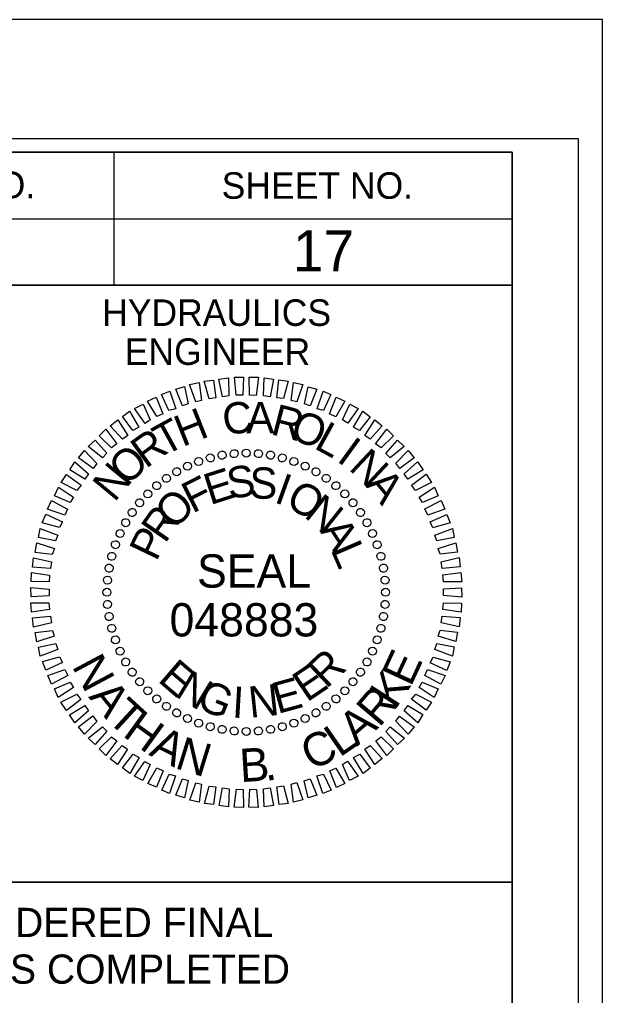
# Model space of a CAD drawing. Extents: x 1647943 to 1651624, y 802691 to 845761.
# Drawn here: x 1650436.5 to 1650546.3, y 803607.1 to 803791 of the extents above; entities that cross this region are included whole.
import ezdxf

# ---------------------------------------------------------------- set-up
doc = ezdxf.new("R2010")
doc.units = 0
for name, color, linetype in [('Default', 7, 'Continuous'), ('Old_Level_2', 7, 'Continuous'), ('Sheet Cutting Line CELL', 7, 'Continuous'), ('Sheet Data Field CELL', 7, 'Continuous'), ('Sheet Plot Border Inside CELL', 7, 'Continuous'), ('Sheet Plot Border Outside CELL', 7, 'Continuous'), ('Sheet Profile CELL', 7, 'Continuous'), ('Sheet Profile Grid Major CELL', 7, 'Continuous'), ('Sheet Sticker Exception Certification CELL', 7, 'Continuous')]:
    doc.layers.add(name, color=color, linetype=linetype)

msp = doc.modelspace()

# ---------------------------------------------------------------- linework, layer by layer
at = {"layer": 'Old_Level_2'}
for p, q in [((1650476.94, 803709.25), (1650476.94, 803709.25)), ((1650479.24, 803709.34), (1650479.24, 803709.34)), ((1650481.55, 803709.22), (1650481.55, 803709.22)), ((1650470.22, 803707.77), (1650470.22, 803707.77)), ((1650472.41, 803708.44), (1650472.41, 803708.44)), ((1650474.7, 803708.89), (1650474.7, 803708.89)), ((1650483.8, 803708.9), (1650483.8, 803708.9)), ((1650486.01, 803708.46), (1650486.01, 803708.46)), ((1650488.21, 803707.77), (1650488.21, 803707.77)), ((1650466.13, 803705.82), (1650466.13, 803705.82)), ((1650468.15, 803706.9), (1650468.15, 803706.9)), ((1650490.32, 803706.87), (1650490.32, 803706.87)), ((1650492.38, 803705.86), (1650492.38, 803705.86)), ((1650464.16, 803704.58), (1650464.16, 803704.58)), ((1650494.28, 803704.58), (1650494.28, 803704.58)), ((1650460.66, 803701.64), (1650460.66, 803701.64)), ((1650462.35, 803703.24), (1650462.35, 803703.24)), ((1650496.14, 803703.2), (1650496.14, 803703.2)), ((1650497.79, 803701.66), (1650497.79, 803701.66)), ((1650459.12, 803699.99), (1650459.12, 803699.99)), ((1650499.38, 803699.96), (1650499.38, 803699.96)), ((1650457.74, 803698.14), (1650457.74, 803698.14)), ((1650500.72, 803698.16), (1650500.72, 803698.16)), ((1650456.46, 803696.23), (1650456.46, 803696.23)), ((1650501.96, 803696.19), (1650501.96, 803696.19)), ((1650455.45, 803694.18), (1650455.45, 803694.18)), ((1650503.04, 803694.17), (1650503.04, 803694.17)), ((1650454.55, 803692.07), (1650454.55, 803692.07)), ((1650503.91, 803692.09), (1650503.91, 803692.09)), ((1650453.85, 803689.86), (1650453.85, 803689.86)), ((1650504.58, 803689.91), (1650504.58, 803689.91)), ((1650453.42, 803687.66), (1650453.42, 803687.66)), ((1650505.04, 803687.62), (1650505.04, 803687.62)), ((1650453.1, 803685.4), (1650453.1, 803685.4)), ((1650505.39, 803685.37), (1650505.39, 803685.37)), ((1650452.98, 803683.1), (1650452.98, 803683.1)), ((1650479.23, 803683.09), (1650479.23, 803683.09)), ((1650505.48, 803683.07), (1650505.48, 803683.07)), ((1650453.07, 803680.8), (1650453.07, 803680.8)), ((1650505.37, 803680.77), (1650505.37, 803680.77)), ((1650453.42, 803678.56), (1650453.42, 803678.56)), ((1650505.04, 803678.52), (1650505.04, 803678.52)), ((1650453.88, 803676.26), (1650453.88, 803676.26)), ((1650504.61, 803676.31), (1650504.61, 803676.31)), ((1650454.55, 803674.08), (1650454.55, 803674.08)), ((1650503.92, 803674.1), (1650503.92, 803674.1)), ((1650455.42, 803672), (1650455.42, 803672)), ((1650503.01, 803672), (1650503.01, 803672)), ((1650456.5, 803669.98), (1650456.5, 803669.98)), ((1650502, 803669.94), (1650502, 803669.94)), ((1650457.74, 803668.02), (1650457.74, 803668.02)), ((1650500.73, 803668.03), (1650500.73, 803668.03)), ((1650459.08, 803666.21), (1650459.08, 803666.21)), ((1650499.35, 803666.18), (1650499.35, 803666.18)), ((1650460.68, 803664.51), (1650460.68, 803664.51)), ((1650497.81, 803664.53), (1650497.81, 803664.53)), ((1650462.32, 803662.97), (1650462.32, 803662.97)), ((1650464.18, 803661.59), (1650464.18, 803661.59)), ((1650494.3, 803661.59), (1650494.3, 803661.59)), ((1650496.11, 803662.93), (1650496.11, 803662.93)), ((1650466.08, 803660.32), (1650466.08, 803660.32)), ((1650468.14, 803659.31), (1650468.14, 803659.31)), ((1650492.34, 803660.36), (1650492.34, 803660.36)), ((1650470.25, 803658.4), (1650470.25, 803658.4)), ((1650472.46, 803657.71), (1650472.46, 803657.71)), ((1650486.05, 803657.74), (1650486.05, 803657.74)), ((1650488.24, 803658.4), (1650488.24, 803658.4)), ((1650490.32, 803659.28), (1650490.32, 803659.28)), ((1650474.66, 803657.28), (1650474.66, 803657.28)), ((1650476.92, 803656.95), (1650476.92, 803656.95)), ((1650479.22, 803656.83), (1650479.22, 803656.83)), ((1650481.52, 803656.93), (1650481.52, 803656.93)), ((1650483.76, 803657.28), (1650483.76, 803657.28))]:
    msp.add_line(p, q, dxfattribs=at)
for points in [[(1650467.22, 803718.23), (1650465.96, 803721.34), (1650467.57, 803721.84), (1650468.31, 803718.61)], [(1650469.71, 803718.95), (1650468.56, 803722.23), (1650470.33, 803722.62), (1650470.81, 803719.23)], [(1650472.21, 803719.57), (1650471.32, 803722.9), (1650473.04, 803723.09), (1650473.47, 803719.75)], [(1650474.72, 803719.93), (1650474.08, 803723.26), (1650475.86, 803723.5), (1650475.97, 803720.11)], [(1650477.33, 803720.24), (1650477.01, 803723.63), (1650478.73, 803723.61), (1650478.58, 803720.21)], [(1650479.84, 803720.23), (1650479.78, 803723.63), (1650481.5, 803723.6), (1650481.09, 803720.2)], [(1650482.45, 803720.12), (1650482.6, 803723.52), (1650484.34, 803723.23), (1650483.71, 803719.93)], [(1650484.97, 803719.74), (1650485.38, 803723.1), (1650487.11, 803722.86), (1650486.23, 803719.61)], [(1650487.65, 803719.21), (1650488.11, 803722.62), (1650489.9, 803722.23), (1650488.75, 803718.97)], [(1650464.67, 803717.35), (1650463.26, 803720.36), (1650464.82, 803721.01), (1650465.97, 803717.68)], [(1650490.17, 803718.58), (1650490.9, 803721.83), (1650492.53, 803721.34), (1650491.27, 803718.23)], [(1650492.54, 803717.68), (1650493.68, 803720.99), (1650495.16, 803720.39), (1650493.75, 803717.33)], [(1650460.16, 803714.92), (1650458.18, 803717.71), (1650459.79, 803718.57), (1650461.15, 803715.56)], [(1650462.39, 803716.21), (1650460.66, 803719.11), (1650462.27, 803719.87), (1650463.53, 803716.7)], [(1650494.91, 803716.72), (1650496.16, 803719.83), (1650497.79, 803719.13), (1650496.07, 803716.17)], [(1650497.33, 803715.56), (1650498.69, 803718.57), (1650500.28, 803717.71), (1650498.34, 803714.95)], [(1650457.89, 803713.57), (1650455.9, 803716.2), (1650457.25, 803717.22), (1650459.02, 803714.22)], [(1650499.4, 803714.19), (1650501.17, 803717.25), (1650502.55, 803716.18), (1650500.56, 803713.58)], [(1650455.93, 803711.97), (1650453.63, 803714.44), (1650455.03, 803715.56), (1650456.91, 803712.66)], [(1650501.57, 803712.66), (1650503.45, 803715.57), (1650504.83, 803714.44), (1650502.57, 803711.94)], [(1650453.86, 803710.31), (1650451.52, 803712.57), (1650452.76, 803713.85), (1650454.84, 803711.06)], [(1650503.58, 803711.07), (1650505.68, 803713.83), (1650506.96, 803712.59), (1650504.59, 803710.3)], [(1650452.17, 803708.45), (1650449.47, 803710.55), (1650450.75, 803711.77), (1650452.99, 803709.3)], [(1650505.5, 803709.27), (1650507.7, 803711.77), (1650508.98, 803710.54), (1650506.3, 803708.45)], [(1650450.37, 803706.43), (1650447.62, 803708.42), (1650448.75, 803709.8), (1650451.09, 803707.38)], [(1650507.36, 803707.42), (1650509.72, 803709.82), (1650510.85, 803708.43), (1650508.11, 803706.39)], [(1650448.84, 803704.42), (1650445.99, 803706.14), (1650446.95, 803707.68), (1650449.5, 803705.42)], [(1650508.96, 803705.41), (1650511.49, 803707.65), (1650512.51, 803706.15), (1650509.61, 803704.43)], [(1650447.31, 803702.3), (1650444.35, 803703.81), (1650445.37, 803705.3), (1650448.13, 803703.25)], [(1650510.36, 803703.29), (1650513.1, 803705.33), (1650514.12, 803703.78), (1650511.11, 803702.26)], [(1650446.09, 803700.03), (1650443.09, 803701.28), (1650443.85, 803702.92), (1650446.7, 803701.03)], [(1650511.76, 803701.02), (1650514.66, 803702.9), (1650515.36, 803701.29), (1650512.41, 803700.03)], [(1650445.09, 803697.6), (1650441.83, 803698.75), (1650442.58, 803700.38), (1650445.59, 803698.76)], [(1650512.85, 803698.79), (1650515.9, 803700.41), (1650516.61, 803698.75), (1650513.39, 803697.65)], [(1650444.08, 803695.29), (1650440.83, 803696.17), (1650441.48, 803697.8), (1650444.64, 803696.39)], [(1650513.83, 803696.35), (1650516.99, 803697.76), (1650517.6, 803696.15), (1650514.37, 803695.26)], [(1650443.34, 803692.76), (1650440.09, 803693.39), (1650440.43, 803695.12), (1650443.74, 803693.87)], [(1650514.71, 803693.85), (1650518.03, 803695.11), (1650518.38, 803693.39), (1650515.09, 803692.76)], [(1650442.71, 803690.24), (1650439.46, 803690.6), (1650439.79, 803692.39), (1650443.11, 803691.35)], [(1650515.38, 803691.35), (1650518.66, 803692.4), (1650519, 803690.63), (1650515.71, 803690.26)], [(1650442.34, 803687.57), (1650438.99, 803687.82), (1650439.16, 803689.6), (1650442.58, 803688.83)], [(1650515.89, 803688.85), (1650519.28, 803689.64), (1650519.47, 803687.87), (1650516.13, 803687.6)], [(1650442.12, 803685.05), (1650438.72, 803685.1), (1650438.79, 803686.83), (1650442.2, 803686.31)], [(1650516.25, 803686.35), (1650519.64, 803686.82), (1650519.78, 803685.05), (1650516.38, 803685.09)], [(1650442.11, 803682.44), (1650438.72, 803682.22), (1650438.69, 803684), (1650442.09, 803683.69)], [(1650516.35, 803683.73), (1650519.75, 803683.95), (1650519.78, 803682.17), (1650516.37, 803682.48)], [(1650442.21, 803679.83), (1650438.82, 803679.35), (1650438.68, 803681.12), (1650442.08, 803681.08)], [(1650516.34, 803681.12), (1650519.74, 803681.07), (1650519.67, 803679.35), (1650516.26, 803679.86)], [(1650442.57, 803677.32), (1650439.18, 803676.53), (1650438.99, 803678.3), (1650442.34, 803678.57)], [(1650516.13, 803678.61), (1650519.48, 803678.35), (1650519.3, 803676.57), (1650515.89, 803677.35)], [(1650443.08, 803674.82), (1650439.81, 803673.77), (1650439.46, 803675.54), (1650442.75, 803675.91)], [(1650515.75, 803675.93), (1650519, 803675.57), (1650518.67, 803673.79), (1650515.36, 803674.83)], [(1650443.75, 803672.32), (1650440.43, 803671.06), (1650440.08, 803672.78), (1650443.37, 803673.41)], [(1650515.12, 803673.41), (1650518.37, 803672.79), (1650518.04, 803671.06), (1650514.72, 803672.31)], [(1650444.63, 803669.83), (1650441.47, 803668.41), (1650440.86, 803670.02), (1650444.09, 803670.92)], [(1650514.38, 803670.89), (1650517.64, 803670), (1650516.98, 803668.37), (1650513.82, 803669.78)], [(1650445.62, 803667.39), (1650442.56, 803665.76), (1650441.85, 803667.42), (1650445.07, 803668.53)], [(1650513.37, 803668.57), (1650516.64, 803667.42), (1650515.88, 803665.79), (1650512.87, 803667.41)], [(1650446.7, 803665.16), (1650443.81, 803663.28), (1650443.1, 803664.88), (1650446.06, 803666.14)], [(1650512.37, 803666.15), (1650515.37, 803664.89), (1650514.62, 803663.26), (1650511.76, 803665.14)], [(1650448.1, 803662.88), (1650445.37, 803660.84), (1650444.34, 803662.4), (1650447.35, 803663.91)], [(1650511.15, 803663.88), (1650514.11, 803662.36), (1650513.09, 803660.88), (1650510.33, 803662.92)], [(1650449.5, 803660.76), (1650446.97, 803658.52), (1650445.96, 803660.02), (1650448.85, 803661.74)], [(1650509.62, 803661.76), (1650512.48, 803660.03), (1650511.51, 803658.5), (1650508.96, 803660.75)], [(1650451.1, 803658.75), (1650448.74, 803656.35), (1650447.62, 803657.75), (1650450.35, 803659.78)], [(1650508.09, 803659.74), (1650510.84, 803657.75), (1650509.72, 803656.37), (1650507.37, 803658.79)], [(1650452.97, 803656.9), (1650450.76, 803654.4), (1650449.48, 803655.63), (1650452.17, 803657.72)], [(1650506.29, 803657.72), (1650509, 803655.63), (1650507.71, 803654.4), (1650505.47, 803656.87)], [(1650454.88, 803655.1), (1650452.78, 803652.35), (1650451.51, 803653.58), (1650453.87, 803655.87)], [(1650504.6, 803655.86), (1650506.94, 803653.6), (1650505.71, 803652.33), (1650503.62, 803655.12)], [(1650456.89, 803653.52), (1650455.01, 803650.61), (1650453.63, 803651.73), (1650455.89, 803654.23)], [(1650502.54, 803654.21), (1650504.83, 803651.74), (1650503.44, 803650.61), (1650501.56, 803653.51)], [(1650459.06, 803651.98), (1650457.29, 803648.92), (1650455.91, 803649.99), (1650457.9, 803652.59)], [(1650500.58, 803652.6), (1650502.56, 803649.97), (1650501.22, 803648.95), (1650499.44, 803651.96)], [(1650461.13, 803650.61), (1650459.77, 803647.6), (1650458.18, 803648.46), (1650460.12, 803651.22)], [(1650498.3, 803651.26), (1650500.28, 803648.47), (1650498.68, 803647.6), (1650497.32, 803650.61)], [(1650463.55, 803649.45), (1650462.3, 803646.34), (1650460.67, 803647.04), (1650462.39, 803650)], [(1650465.92, 803648.5), (1650464.78, 803645.18), (1650463.3, 803645.78), (1650464.72, 803648.84)], [(1650493.79, 803648.82), (1650495.2, 803645.82), (1650493.65, 803645.16), (1650492.49, 803648.49)], [(1650496.07, 803649.96), (1650497.8, 803647.06), (1650496.19, 803646.3), (1650494.93, 803649.47)], [(1650468.29, 803647.6), (1650467.57, 803644.34), (1650465.94, 803644.83), (1650467.19, 803647.94)], [(1650470.81, 803646.96), (1650470.35, 803643.55), (1650468.57, 803643.94), (1650469.71, 803647.2)], [(1650473.49, 803646.43), (1650473.08, 803643.08), (1650471.35, 803643.31), (1650472.23, 803646.57)], [(1650486.25, 803646.6), (1650487.14, 803643.27), (1650485.42, 803643.08), (1650485, 803646.42)], [(1650488.75, 803647.22), (1650489.9, 803643.95), (1650488.13, 803643.55), (1650487.65, 803646.94)], [(1650491.25, 803647.94), (1650492.5, 803644.83), (1650490.89, 803644.33), (1650490.15, 803647.56)], [(1650476.01, 803646.06), (1650475.86, 803642.65), (1650474.13, 803642.94), (1650474.75, 803646.24)], [(1650478.62, 803645.95), (1650478.68, 803642.55), (1650476.96, 803642.57), (1650477.37, 803645.98)], [(1650481.13, 803645.94), (1650481.46, 803642.54), (1650479.73, 803642.57), (1650479.88, 803645.97)], [(1650483.74, 803646.24), (1650484.38, 803642.91), (1650482.6, 803642.67), (1650482.49, 803646.07)]]:
    msp.add_lwpolyline(points, close=True, dxfattribs=at)
for centre, major_axis in [((1650472.44, 803708.42), (-0.195, 0.727)), ((1650474.68, 803708.92), (-0.131, 0.742)), ((1650476.95, 803709.21), (-0.066, 0.75)), ((1650479.23, 803709.31), (0, 0.753)), ((1650481.52, 803709.21), (0.066, 0.75)), ((1650483.79, 803708.92), (0.131, 0.742)), ((1650486.02, 803708.42), (0.195, 0.727)), ((1650468.15, 803706.86), (-0.318, 0.682)), ((1650470.26, 803707.73), (-0.258, 0.708)), ((1650488.2, 803707.73), (0.258, 0.708)), ((1650490.32, 803706.86), (0.318, 0.682)), ((1650464.19, 803704.57), (-0.432, 0.617)), ((1650466.12, 803705.8), (-0.376, 0.652)), ((1650492.35, 803705.8), (0.376, 0.652)), ((1650494.27, 803704.57), (0.432, 0.617)), ((1650462.37, 803703.18), (-0.484, 0.577)), ((1650496.09, 803703.18), (0.484, 0.577)), ((1650460.69, 803701.63), (-0.532, 0.532)), ((1650497.78, 803701.63), (0.532, 0.532)), ((1650459.14, 803699.95), (-0.577, 0.484)), ((1650499.32, 803699.95), (0.577, 0.484)), ((1650457.75, 803698.13), (-0.617, 0.432)), ((1650500.72, 803698.13), (0.617, 0.432)), ((1650456.52, 803696.2), (-0.652, 0.376)), ((1650501.95, 803696.2), (0.652, 0.376)), ((1650455.46, 803694.17), (-0.682, 0.318)), ((1650503, 803694.17), (0.682, 0.318)), ((1650454.59, 803692.06), (-0.708, 0.258)), ((1650503.88, 803692.06), (0.708, 0.258)), ((1650453.9, 803689.87), (-0.727, 0.195)), ((1650504.57, 803689.87), (0.727, 0.195)), ((1650453.4, 803687.64), (-0.742, 0.131)), ((1650505.06, 803687.64), (0.742, 0.131)), ((1650453.1, 803685.37), (-0.75, 0.066)), ((1650505.36, 803685.37), (0.75, 0.066)), ((1650453, 803683.09), (-0.753, 0)), ((1650505.46, 803683.09), (0.753, 0)), ((1650453.1, 803680.8), (-0.75, -0.066)), ((1650505.36, 803680.8), (0.75, -0.066)), ((1650453.4, 803678.53), (-0.742, -0.131)), ((1650505.06, 803678.53), (0.742, -0.131)), ((1650453.9, 803676.3), (-0.727, -0.195)), ((1650504.57, 803676.3), (0.727, -0.195)), ((1650454.59, 803674.12), (-0.708, -0.258)), ((1650503.88, 803674.12), (0.708, -0.258)), ((1650455.46, 803672), (-0.682, -0.318)), ((1650503, 803672), (0.682, -0.318)), ((1650456.52, 803669.97), (-0.652, -0.376)), ((1650501.95, 803669.97), (0.652, -0.376)), ((1650457.75, 803668.04), (-0.617, -0.432)), ((1650500.72, 803668.04), (0.617, -0.432)), ((1650459.14, 803666.23), (-0.577, -0.484)), ((1650499.32, 803666.23), (0.577, -0.484)), ((1650460.69, 803664.54), (-0.532, -0.532)), ((1650497.78, 803664.54), (0.532, -0.532)), ((1650462.37, 803662.99), (-0.484, -0.577)), ((1650496.09, 803662.99), (0.484, -0.577)), ((1650464.19, 803661.6), (-0.432, -0.617)), ((1650466.12, 803660.37), (-0.376, -0.652)), ((1650492.35, 803660.37), (0.376, -0.652)), ((1650494.27, 803661.6), (0.432, -0.617)), ((1650468.15, 803659.32), (-0.318, -0.682)), ((1650490.32, 803659.32), (0.318, -0.682)), ((1650470.26, 803658.44), (-0.258, -0.708)), ((1650472.44, 803657.75), (-0.195, -0.727)), ((1650474.68, 803657.26), (-0.131, -0.742)), ((1650476.95, 803656.96), (-0.066, -0.75)), ((1650479.23, 803656.86), (0, -0.753)), ((1650481.52, 803656.96), (0.066, -0.75)), ((1650483.79, 803657.26), (0.131, -0.742)), ((1650486.02, 803657.75), (0.195, -0.727)), ((1650488.2, 803658.44), (0.258, -0.708))]:
    msp.add_ellipse(centre, major_axis=major_axis, ratio=0.999708, dxfattribs=at)
at = {"layer": 'Sheet Cutting Line CELL'}
msp.add_line((1650546.28, 803791.02), (1648862.28, 803791.02), dxfattribs=at)
at = {"layer": 'Sheet Plot Border Inside CELL'}
msp.add_lwpolyline([(1648875.28, 802713.47), (1650541.78, 802713.47), (1650541.78, 803768.57), (1648875.28, 803768.57)], close=True, dxfattribs=at)
at = {"layer": 'Sheet Plot Border Outside CELL'}
msp.add_lwpolyline([(1648862.28, 802691.02), (1650546.28, 802691.02), (1650546.28, 803791.02), (1648862.28, 803791.02)], close=True, dxfattribs=at)
at = {"layer": 'Sheet Profile CELL'}
for p, q in [((1650454.28, 803765.97), (1650454.28, 803740.97)), ((1650329.23, 803753.47), (1650529.28, 803753.47))]:
    msp.add_line(p, q, dxfattribs=at)
for points in [[(1650529.28, 803766.02), (1649029.28, 803766.02), (1649029.28, 802716.02), (1650529.28, 802716.02)], [(1650329.23, 803766.02), (1650529.28, 803766.02), (1650529.28, 803740.97), (1650329.23, 803740.97)], [(1650429.28, 803740.97), (1650529.28, 803740.97), (1650529.28, 803628.47), (1650429.28, 803628.47)]]:
    msp.add_lwpolyline(points, close=True, dxfattribs=at)
at = {"layer": 'Sheet Profile Grid Major CELL'}
msp.add_lwpolyline([(1650479.28, 803604.97), (1650479.28, 803266.02), (1650529.28, 803266.02), (1650529.28, 803616.02)], dxfattribs=at)
at = {"layer": 'Sheet Sticker Exception Certification CELL'}
for p, q in [((1650329.23, 803628.47), (1650529.27, 803628.47)), ((1650329.23, 803628.47), (1650529.27, 803628.47)), ((1650529.27, 803628.46), (1650529.27, 803604.96)), ((1650529.27, 803628.46), (1650529.27, 803604.96))]:
    msp.add_line(p, q, dxfattribs=at)

# ---------------------------------------------------------------- texts
at = {"layer": 'Default'}
for s, rotation, p in [('E', 65.2198, (1650510.2, 803665.13)), ('N', 298.0773, (1650446.31, 803669.19)), ('K', 57.024, (1650507.33, 803660.9)), ('A', 308.6891, (1650449.42, 803663.36)), ('R', 49.6233, (1650504.25, 803657.47)), ('T', 317.4354, (1650452.76, 803659.05)), ('H', 324.1633, (1650455.75, 803656.11)), ('A', 40.877, (1650500.07, 803653.97)), ('L', 34.6689, (1650496.8, 803651.89)), ('A', 334.0411, (1650460.72, 803652.48)), ('N', 342.7874, (1650465.58, 803650.01)), ('C', 25.1886, (1650491.43, 803649.42)), ('B', 3.4911, (1650478.14, 803647.31)), ('.', 11.1059, (1650482.89, 803647.47))]:
    msp.add_text(s, height=6.27, rotation=rotation, dxfattribs=at).set_placement(p)
at = {"layer": 'Old_Level_2'}
for s, rotation, p in [('C', 7.2199, (1650475.11, 803712.67)), ('A', 0.0203, (1650479.23, 803713.05)), ('R', 345.6211, (1650483.63, 803712.92)), ('H', 21.6195, (1650467.2, 803710.44)), ('O', 338.4212, (1650487.14, 803712.2)), ('T', 28.8198, (1650463.83, 803708.65)), ('L', 331.2209, (1650491.78, 803710.34)), ('R', 36.0205, (1650460.31, 803706.29)), ('I', 324.0201, (1650496.06, 803707.91)), ('O', 43.2217, (1650456.76, 803702.99)), ('N', 316.8189, (1650498.33, 803706.33)), ('N', 50.4235, (1650454.41, 803699.91)), ('E', 17.6111, (1650472.41, 803699.49)), ('S', 8.2556, (1650476, 803700.65)), ('S', 358.9004, (1650479.76, 803700.77)), ('I', 340.1896, (1650484.27, 803700.12)), ('A', 309.6172, (1650501.47, 803703.29)), ('F', 26.967, (1650469.09, 803697.87)), ('O', 330.8335, (1650486.37, 803699.42)), ('O', 45.6812, (1650465.69, 803694.72)), ('N', 321.4766, (1650489.91, 803697.39)), ('R', 55.0397, (1650463.91, 803692.13)), ('P', 64.3989, (1650462.29, 803688.75)), ('A', 302.7603, (1650492.94, 803694.73)), ('L', 293.4009, (1650495.04, 803691.15)), ('E', 319.2769, (1650462.37, 803666.42)), ('R', 43.4814, (1650494.3, 803664.78)), ('E', 34.1241, (1650490.63, 803662.26)), ('N', 328.634, (1650465.56, 803663.65)), ('E', 15.4118, (1650485.12, 803660.13)), ('G', 337.9902, (1650469.57, 803661.37)), ('I', 356.7012, (1650476.45, 803659.5)), ('N', 6.0564, (1650479.96, 803659.41))]:
    msp.add_text(s, height=5.9, rotation=rotation, dxfattribs=at).set_placement(p)
for s, height, p in [('SEAL', 6.273, (1650469.96, 803683.97)), ('048883', 6.275, (1650464.78, 803674.77))]:
    msp.add_text(s, height=height, dxfattribs=at).set_placement(p)
at = {"layer": 'Sheet Data Field CELL'}
msp.add_text('17', height=7.75, dxfattribs=at).set_placement((1650488, 803743.57))
at = {"layer": 'Sheet Profile CELL'}
for s, height, p in [('PROJECT REFERENCE NO.', 5.0001, (1650351.44, 803757.34)), ('SHEET NO.', 5, (1650474.59, 803757.24)), ('HYDRAULICS', 5, (1650452.09, 803733.29)), ('ENGINEER', 5, (1650456.34, 803725.94))]:
    msp.add_text(s, height=height, dxfattribs=at).set_placement(p)
at = {"layer": 'Sheet Sticker Exception Certification CELL'}
for s, p in [('DOCUMENT NOT CONSIDERED FINAL', (1650350.3, 803618.13)), ('DOCUMENT NOT CONSIDERED FINAL', (1650350.3, 803618.13)), ('UNLESS ALL SIGNATURES COMPLETED', (1650345.23, 803609.33)), ('UNLESS ALL SIGNATURES COMPLETED', (1650345.23, 803609.33))]:
    msp.add_text(s, height=5.5, dxfattribs=at).set_placement(p)

doc.saveas('drawing.dxf')
